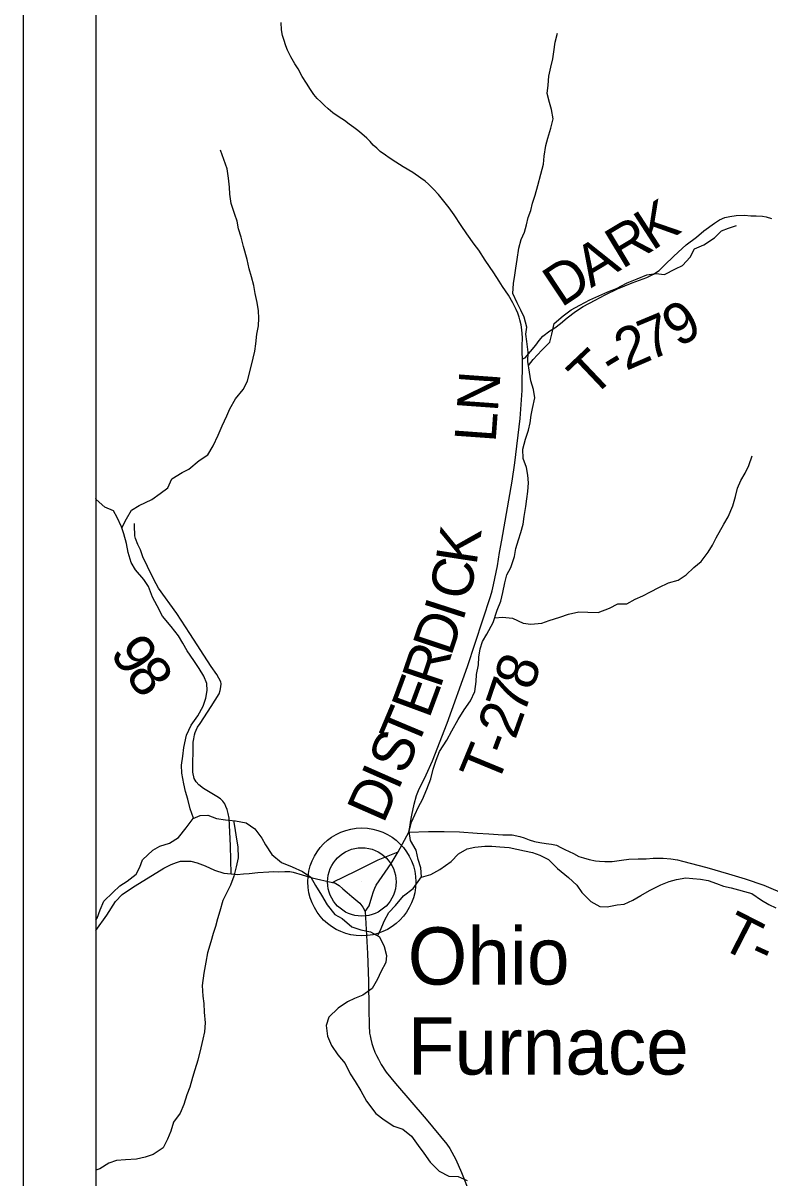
# Model space of a CAD drawing. Extents: x 0 to 44, y -23.8 to 22.
# Drawn here: x 2 to 3.029, y 14.979 to 16.572 of the extents above; entities that cross this region are included whole.
import ezdxf

# ---------------------------------------------------------------- set-up
doc = ezdxf.new("R2010")
doc.units = 0
for name, color, linetype in [('Default', 7, 'Continuous'), ('GM_X_County_Road', 7, 'Continuous'), ('GM_X_County_Text', 7, 'Continuous'), ('GM_X_Minor_River', 7, 'Continuous'), ('GM_X_Township_Road', 7, 'Continuous'), ('GM_X_Township_Road_Text', 7, 'Continuous'), ('GM_X_Unincorporated', 7, 'Continuous'), ('GM_X_Unincorporated_Location', 7, 'Continuous'), ('GM_X_Unincorporated_Text', 7, 'Continuous'), ('SH_Cut_Line', 7, 'Continuous'), ('SH_Data', 7, 'Continuous')]:
    doc.layers.add(name, color=color, linetype=linetype)

msp = doc.modelspace()

# ---------------------------------------------------------------- linework, layer by layer
at = {"layer": 'Default'}
msp.add_lwpolyline([(2.3497, 20.9), (2.1, 20.9), (2.1, 14.1), (2.838, 14.1), (3.0317, 14.1856), (3.8639, 14.5533), (4.3443, 14.7655), (4.4538, 14.8144), (4.856, 14.9939), (4.5387, 15.7097), (4.3476, 16.1408), (4.1422, 16.6361), (4.026, 16.9163), (3.7907, 17.4383), (3.763, 17.5087), (3.455, 18.29), (3.1789, 18.9421), (3.1321, 19.0527), (3.0496, 19.2474), (3.0092, 19.3427), (2.8013, 19.8369), (2.472, 20.6113)], close=True, dxfattribs=at)
at = {"layer": 'GM_X_County_Road'}
msp.add_lwpolyline([(2.1, 15.3207), (2.1152, 15.3415), (2.1275, 15.3607), (2.1364, 15.37), (2.152, 15.3807), (2.1722, 15.3933), (2.1939, 15.4064), (2.204, 15.4117), (2.2112, 15.4141), (2.2167, 15.4159), (2.224, 15.4163), (2.2312, 15.4161), (2.2399, 15.4137), (2.2511, 15.4096), (2.2636, 15.4038), (2.2765, 15.3997), (2.2866, 15.3987), (2.2951, 15.3979), (2.3038, 15.3985), (2.3117, 15.3993), (2.3236, 15.4004), (2.3386, 15.4014), (2.3453, 15.4018), (2.3519, 15.4016), (2.3606, 15.402), (2.3675, 15.402), (2.3721, 15.4008), (2.3847, 15.3973), (2.3984, 15.3929), (2.4265, 15.3869), (2.4285, 15.3866), (2.4354, 15.3824), (2.4407, 15.3779), (2.4465, 15.3729), (2.4532, 15.3672), (2.4639, 15.3581), (2.4684, 15.3526), (2.4716, 15.3466), (2.4744, 15.2888), (2.4758, 15.2504), (2.4764, 15.2126), (2.4768, 15.1893), (2.4775, 15.179), (2.4783, 15.175), (2.4793, 15.1707), (2.4805, 15.1645), (2.4823, 15.1592), (2.4849, 15.1529), (2.4868, 15.1479), (2.4896, 15.1432), (2.4936, 15.1355), (2.5003, 15.1252), (2.513, 15.1095), (2.5557, 15.0601), (2.5838, 15.0256), (2.5882, 15.0199), (2.5965, 15.0046), (2.6042, 14.9868), (2.6157, 14.9579)], dxfattribs=at)
at = {"layer": 'GM_X_Minor_River'}
for points in [[(2.7301, 16.5227), (2.7313, 16.5322), (2.7332, 16.5455), (2.7367, 16.558)], [(2.4886, 15.313), (2.492, 15.3199), (2.4981, 15.3343), (2.5039, 15.3453), (2.5134, 15.3551), (2.5244, 15.3683), (2.5377, 15.3785), (2.5492, 15.3943), (2.5481, 15.4068), (2.5444, 15.4186), (2.5418, 15.4312), (2.534, 15.4445), (2.5322, 15.457), (2.5353, 15.4699), (2.5399, 15.4801), (2.5449, 15.4911), (2.5502, 15.5013), (2.5564, 15.5153), (2.5621, 15.5297), (2.5652, 15.5429), (2.5691, 15.5554), (2.5737, 15.5675), (2.584, 15.583), (2.5909, 15.5959), (2.5997, 15.6113), (2.6077, 15.625), (2.6165, 15.6374), (2.6226, 15.6499), (2.6242, 15.6639), (2.625, 15.6734), (2.6274, 15.6867), (2.6282, 15.6973), (2.6301, 15.709), (2.6332, 15.7189), (2.639, 15.7291), (2.6478, 15.7453), (2.6535, 15.7624), (2.6582, 15.7745), (2.6613, 15.7866), (2.664, 15.7998), (2.6667, 15.8112), (2.6721, 15.821), (2.6774, 15.8362), (2.679, 15.8475), (2.6825, 15.8593), (2.686, 15.8695), (2.6891, 15.8809), (2.6906, 15.8915), (2.693, 15.9051), (2.6942, 15.9157), (2.6958, 15.926), (2.6966, 15.9377), (2.6955, 15.9483), (2.6937, 15.959), (2.6892, 15.9715), (2.6886, 15.9844), (2.6924, 15.998), (2.6963, 16.0105), (2.699, 16.0208), (2.7002, 16.031), (2.7021, 16.0405), (2.7053, 16.0552), (2.7034, 16.0666), (2.6997, 16.0784), (2.6979, 16.0905), (2.6957, 16.105), (2.6962, 16.1182), (2.694, 16.1327), (2.6929, 16.1429), (2.6941, 16.1524), (2.6904, 16.1664), (2.686, 16.176), (2.6811, 16.1862), (2.6751, 16.1992), (2.676, 16.2128), (2.6779, 16.2242), (2.6791, 16.234), (2.6807, 16.2458), (2.6831, 16.2617), (2.6866, 16.2734), (2.6912, 16.2836), (2.6939, 16.2939), (2.6962, 16.3037), (2.6997, 16.3136), (2.702, 16.3238), (2.7055, 16.3348), (2.7093, 16.348), (2.7136, 16.3635), (2.7171, 16.3775), (2.7183, 16.3885), (2.7206, 16.4029), (2.7233, 16.4132), (2.7272, 16.4272), (2.7303, 16.44), (2.7281, 16.4526), (2.7255, 16.4625), (2.7222, 16.4746), (2.7234, 16.4864), (2.7246, 16.4989), (2.7273, 16.511), (2.7301, 16.5227)], [(2.1359, 15.8757), (2.1427, 15.8883), (2.1496, 15.9004), (2.1598, 15.9068), (2.1773, 15.915), (2.189, 15.9233), (2.1993, 15.9308), (2.205, 15.9433), (2.2191, 15.952), (2.2286, 15.9568), (2.2426, 15.9689), (2.2544, 15.9764), (2.262, 15.9889), (2.2686, 16.0036), (2.2743, 16.0165), (2.2808, 16.0301), (2.285, 16.0399), (2.2927, 16.0535), (2.3034, 16.0668), (2.3091, 16.0781), (2.3172, 16.1099), (2.3192, 16.1194), (2.3208, 16.1296), (2.322, 16.1429), (2.3243, 16.1542), (2.3248, 16.1649), (2.3244, 16.1751), (2.3226, 16.1865), (2.32, 16.199), (2.3178, 16.21), (2.3149, 16.2218), (2.3116, 16.2332), (2.309, 16.2461), (2.3038, 16.264), (2.3005, 16.2765), (2.2968, 16.2883), (2.2949, 16.2986), (2.2916, 16.3081), (2.2868, 16.3233), (2.285, 16.3358), (2.2843, 16.3456), (2.2832, 16.3582), (2.281, 16.3707), (2.2766, 16.384), (2.2721, 16.3965)], [(2.6966, 16.0996), (2.7029, 16.108), (2.7147, 16.1208), (2.7258, 16.1321), (2.7285, 16.1431), (2.732, 16.1575), (2.7445, 16.1684), (2.7552, 16.1763), (2.7673, 16.1831), (2.781, 16.1902), (2.806, 16.2014), (2.8177, 16.2059), (2.8325, 16.2138), (2.8462, 16.2194), (2.8598, 16.2246), (2.8719, 16.2268), (2.884, 16.2252), (2.8992, 16.2331), (2.9087, 16.2376), (2.9194, 16.2493), (2.9255, 16.2606), (2.938, 16.2662), (2.9528, 16.2756), (2.9627, 16.2854), (2.9722, 16.2891), (2.9832, 16.2929)], [(2.65, 15.7518), (2.6607, 15.7528), (2.6743, 15.7512), (2.689, 15.7443), (2.6996, 15.7431), (2.7147, 15.7442), (2.7249, 15.7479), (2.7397, 15.7527), (2.7518, 15.7568), (2.7658, 15.7598), (2.7783, 15.7597), (2.7927, 15.7589), (2.8082, 15.7652), (2.8196, 15.7708), (2.8321, 15.7711), (2.8435, 15.7775), (2.8541, 15.782), (2.8647, 15.7876), (2.8761, 15.7936), (2.8894, 15.8), (2.903, 15.8037), (2.914, 15.8112), (2.9243, 15.821), (2.9345, 15.8293), (2.9441, 15.8421), (2.9502, 15.852), (2.9552, 15.8618), (2.9659, 15.8807), (2.9716, 15.8909), (2.9781, 15.906), (2.982, 15.9189), (2.9847, 15.9303), (2.9893, 15.9412), (2.995, 15.9514), (3, 15.9617), (3.0046, 15.9749)], [(2.235, 15.4754), (2.2302, 15.4884), (2.2269, 15.5017), (2.2236, 15.5123), (2.2214, 15.5226), (2.2188, 15.5374), (2.2181, 15.5484), (2.2201, 15.5609), (2.2213, 15.5727), (2.2252, 15.5897), (2.2317, 15.6037), (2.2408, 15.6165), (2.2481, 15.6298), (2.252, 15.6411), (2.2535, 15.6517), (2.2532, 15.6612), (2.2491, 15.6711), (2.2428, 15.6818), (2.2353, 15.6928), (2.2263, 15.7061), (2.2199, 15.7168), (2.2143, 15.7267), (2.2042, 15.7397), (2.1921, 15.7538), (2.1847, 15.7682), (2.1783, 15.78), (2.1727, 15.7948), (2.1664, 15.8047), (2.1551, 15.8177), (2.1487, 15.828), (2.145, 15.8417), (2.1425, 15.8542), (2.1388, 15.8675), (2.1354, 15.877), (2.1298, 15.8899), (2.1246, 15.8994), (2.1125, 15.9041), (2.1009, 15.9151), (2.1, 15.9164)], [(2.1, 15.335), (2.1019, 15.3375), (2.1061, 15.3492), (2.1111, 15.3609), (2.1236, 15.373), (2.1335, 15.382), (2.1434, 15.3884), (2.1559, 15.3982), (2.1609, 15.408), (2.1647, 15.4179), (2.1788, 15.4314), (2.1883, 15.4367), (2.2019, 15.4408), (2.2141, 15.4487), (2.2248, 15.4619), (2.2343, 15.4751), (2.2438, 15.4792), (2.2544, 15.4795), (2.2664, 15.4749), (2.2789, 15.4729), (2.2929, 15.4717), (2.3076, 15.469), (2.3193, 15.4609), (2.329, 15.448), (2.3339, 15.4385), (2.3429, 15.4255)], [(2.29, 15.472), (2.2917, 15.4615), (2.2935, 15.4493), (2.2961, 15.4357), (2.2964, 15.4209), (2.2936, 15.4084), (2.2902, 15.3955), (2.2859, 15.383), (2.2809, 15.3728), (2.2752, 15.3618), (2.2713, 15.3471), (2.2679, 15.3365), (2.2651, 15.3262), (2.2617, 15.3164), (2.2586, 15.305), (2.254, 15.2899), (2.2516, 15.277), (2.2492, 15.2615), (2.2469, 15.2448), (2.2475, 15.23), (2.249, 15.2198), (2.2493, 15.208), (2.2511, 15.1932), (2.2499, 15.1807), (2.2479, 15.1708), (2.2448, 15.1587), (2.2409, 15.1417), (2.2367, 15.1284), (2.2336, 15.1178), (2.2297, 15.1042), (2.2255, 15.094), (2.2217, 15.0807), (2.2163, 15.0686), (2.2071, 15.0561), (2.2037, 15.0437), (2.1991, 15.0327), (2.1929, 15.0206), (2.1793, 15.0116), (2.1683, 15.0078), (2.1561, 15.0049), (2.141, 15.0042), (2.1285, 15.0035), (2.1183, 14.9994), (2.1058, 14.9919), (2.1, 14.9898)], [(2.5489, 15.3939), (2.5621, 15.3977), (2.5742, 15.4044), (2.5898, 15.4157), (2.6, 15.4263), (2.6122, 15.433), (2.6224, 15.4356), (2.6364, 15.4367), (2.6462, 15.4366), (2.6568, 15.4358), (2.6697, 15.4349), (2.6908, 15.4303), (2.7018, 15.4279), (2.7123, 15.4244), (2.724, 15.4183), (2.7364, 15.4061), (2.7515, 15.3935), (2.7631, 15.3828), (2.7699, 15.3729), (2.7823, 15.3603), (2.7947, 15.3534), (2.8049, 15.353), (2.8186, 15.3559), (2.8284, 15.357), (2.8402, 15.3622), (2.8512, 15.3686), (2.8633, 15.3757), (2.8789, 15.3836), (2.8902, 15.3881), (2.9005, 15.3907), (2.9133, 15.3929), (2.9232, 15.3924), (2.9337, 15.3912), (2.9443, 15.3893), (2.9556, 15.3854), (2.9654, 15.3816), (2.9756, 15.3792), (3.0043, 15.3715), (3.0175, 15.3623), (3.0277, 15.3565), (3.0375, 15.3516)], [(2.3429, 15.4255), (2.3561, 15.4144), (2.3708, 15.4083), (2.3851, 15.4018), (2.3964, 15.3941), (2.4028, 15.3827), (2.4114, 15.3694), (2.4189, 15.3557), (2.4297, 15.3427), (2.4399, 15.337), (2.4531, 15.3255), (2.4655, 15.3212), (2.4788, 15.3185), (2.4912, 15.3116), (2.4975, 15.2983), (2.5009, 15.2861), (2.4997, 15.2763), (2.4932, 15.2634), (2.4886, 15.2536), (2.4809, 15.2407), (2.4684, 15.2313), (2.4566, 15.2269), (2.4472, 15.222), (2.4342, 15.2133), (2.4213, 15.2009), (2.4178, 15.1895), (2.4193, 15.1747), (2.4252, 15.1618), (2.4338, 15.1489), (2.444, 15.137), (2.4507, 15.123), (2.4578, 15.1123), (2.4653, 15.0994), (2.4732, 15.0853), (2.4863, 15.0681), (2.4976, 15.0593), (2.5108, 15.0505), (2.5232, 15.0463), (2.5353, 15.0367), (2.5446, 15.0242), (2.5521, 15.0135), (2.5608, 15.0009), (2.5732, 14.9887), (2.5867, 14.9818), (2.5996, 14.981), (2.612, 14.9756)]]:
    msp.add_lwpolyline(points, dxfattribs=at)
at = {"layer": 'GM_X_Township_Road'}
for points in [[(2.3646, 16.5346), (2.3621, 16.5405), (2.3592, 16.5492), (2.3573, 16.5547), (2.356, 16.5626), (2.3558, 16.5728)], [(2.4716, 15.3466), (2.4768, 15.3543), (2.4805, 15.3668), (2.4827, 15.3743), (2.4847, 15.3791), (2.4866, 15.383), (2.495, 15.3949), (2.5074, 15.4127), (2.5169, 15.4291), (2.5315, 15.4562), (2.5324, 15.4606), (2.5332, 15.4657), (2.5341, 15.4701), (2.5355, 15.4797), (2.5389, 15.4946), (2.5422, 15.5067), (2.546, 15.5159), (2.5502, 15.5245), (2.5556, 15.5352), (2.5644, 15.5544), (2.5843, 15.6064), (2.6124, 15.6845), (2.644, 15.781), (2.6465, 15.7889), (2.6484, 15.7971), (2.6536, 15.8233), (2.6565, 15.8419), (2.6597, 15.8587), (2.6739, 15.9401), (2.6777, 15.9655), (2.6848, 16.0268), (2.6877, 16.0651), (2.6883, 16.1088), (2.6877, 16.1177), (2.6879, 16.1263), (2.6881, 16.1385), (2.6873, 16.1491), (2.6862, 16.1556), (2.6845, 16.1625), (2.6835, 16.1663), (2.6816, 16.172), (2.6795, 16.1767), (2.6748, 16.1859), (2.6689, 16.1967), (2.6609, 16.2087), (2.6561, 16.2162), (2.6487, 16.2274), (2.6367, 16.2451), (2.6279, 16.2586), (2.6216, 16.267), (2.6114, 16.2813), (2.6039, 16.2927), (2.594, 16.3074), (2.5872, 16.3173), (2.5796, 16.3264), (2.5723, 16.3354), (2.5657, 16.343), (2.5588, 16.3497), (2.554, 16.3538), (2.5483, 16.3582), (2.5369, 16.3658), (2.524, 16.3736), (2.5137, 16.3803), (2.5045, 16.3862), (2.4994, 16.3898), (2.4923, 16.3948), (2.4876, 16.3994), (2.4826, 16.4037), (2.4781, 16.4085), (2.4735, 16.4133), (2.467, 16.4192), (2.4613, 16.4237), (2.4558, 16.4279), (2.4493, 16.4327), (2.443, 16.4374), (2.4356, 16.4424), (2.427, 16.4481), (2.4204, 16.4538), (2.4152, 16.4582), (2.4101, 16.4633), (2.4053, 16.4681), (2.4007, 16.4736), (2.396, 16.4805), (2.3905, 16.489), (2.3848, 16.4984), (2.379, 16.5087), (2.3747, 16.5159), (2.3689, 16.5252), (2.3659, 16.5317), (2.3646, 16.5346)], [(2.6883, 16.1088), (2.6921, 16.1103), (2.7068, 16.1277), (2.7114, 16.1344), (2.7164, 16.1403), (2.7259, 16.1476), (2.733, 16.1516), (2.7407, 16.1577), (2.7499, 16.1654), (2.7614, 16.174), (2.7719, 16.1809), (2.7885, 16.1899), (2.8023, 16.197), (2.8192, 16.2056), (2.8395, 16.2138), (2.8594, 16.2209), (2.8686, 16.2255), (2.8764, 16.2307), (2.8844, 16.2383), (2.8963, 16.2498), (2.9026, 16.2561), (2.9139, 16.2663), (2.9281, 16.2768), (2.9382, 16.2852), (2.9528, 16.2961), (2.9599, 16.3005), (2.9673, 16.3036), (2.974, 16.3051), (2.9828, 16.3065), (2.9941, 16.3069), (3.0031, 16.3063), (3.0104, 16.3061), (3.019, 16.3055), (3.0242, 16.3046), (3.0315, 16.3023)], [(2.2866, 15.3987), (2.2858, 15.4371), (2.284, 15.4753), (2.2826, 15.482), (2.2812, 15.4875), (2.2794, 15.4917), (2.2779, 15.4952), (2.2753, 15.4988), (2.2719, 15.502), (2.2668, 15.5055), (2.2484, 15.5162), (2.242, 15.5212), (2.2385, 15.5257), (2.2357, 15.5303), (2.2341, 15.539), (2.2345, 15.5801), (2.2351, 15.5847), (2.2361, 15.5902), (2.2371, 15.5936), (2.2385, 15.5966), (2.2405, 15.6009), (2.2438, 15.6061), (2.259, 15.6293), (2.2701, 15.6468), (2.2715, 15.6516), (2.2725, 15.6567), (2.2731, 15.6605), (2.2725, 15.6635), (2.267, 15.6736), (2.2593, 15.6844), (2.2298, 15.73), (2.212, 15.7575), (2.1866, 15.7927), (2.1803, 15.8044), (2.1716, 15.8224), (2.1651, 15.8358), (2.1617, 15.8455), (2.1583, 15.8527), (2.155, 15.861), (2.1542, 15.8649), (2.154, 15.8685), (2.1534, 15.8752), (2.1536, 15.882)], [(2.5315, 15.4562), (2.5589, 15.4569), (2.5803, 15.4569), (2.6012, 15.4567), (2.6256, 15.4549), (2.6418, 15.4537), (2.661, 15.4525), (2.6739, 15.4523), (2.6844, 15.4503), (2.6907, 15.4483), (2.6972, 15.4456), (2.7049, 15.4432), (2.7123, 15.4418), (2.721, 15.4406), (2.7281, 15.4394), (2.735, 15.4381), (2.7412, 15.4351), (2.7465, 15.4323), (2.7524, 15.4295), (2.7584, 15.4268), (2.7661, 15.4224), (2.7724, 15.4206), (2.7799, 15.4185), (2.7889, 15.4165), (2.7944, 15.4159), (2.8015, 15.4157), (2.8118, 15.4157), (2.8249, 15.4175), (2.8346, 15.4189), (2.8476, 15.4194), (2.8587, 15.4194), (2.8684, 15.4204), (2.8823, 15.4202), (2.8926, 15.4191), (2.9017, 15.4179), (2.9086, 15.4163), (2.9422, 15.4076), (2.9721, 15.3985), (2.9951, 15.3919), (3.0208, 15.3832), (3.0521, 15.3696)], [(2.4265, 15.3869), (2.4304, 15.3892), (2.4393, 15.3933), (2.4627, 15.4048), (2.4894, 15.4179), (2.5169, 15.4291)]]:
    msp.add_lwpolyline(points, dxfattribs=at)
at = {"layer": 'GM_X_Unincorporated'}
for radius in [0.0744, 0.0472]:
    msp.add_circle((2.4668, 15.3875), radius, dxfattribs=at)
at = {"layer": 'GM_X_Unincorporated_Location'}
msp.add_line((2.4668, 15.3875), (2.4668, 15.3875), dxfattribs=at)
at = {"layer": 'SH_Cut_Line'}
msp.add_lwpolyline([(2.1, 20.9), (2.1, 14.1), (2.838, 14.1), (3.0317, 14.1856), (3.8639, 14.5533), (4.3443, 14.7655), (4.4538, 14.8144), (4.856, 14.9939), (4.5387, 15.7097), (4.3476, 16.1408), (4.1422, 16.6361)], dxfattribs=at)
at = {"layer": 'SH_Data'}
for p, q in [((2, 21), (2, 14)), ((2.1, 20.9), (2.1, 14.1))]:
    msp.add_line(p, q, dxfattribs=at)

# ---------------------------------------------------------------- texts
at = {"layer": 'GM_X_County_Text'}
msp.add_text('SCIOTO COUNTY', height=0.189394, rotation=23.8999, dxfattribs=at).set_placement((2.9443, 14.3021))
at = {"layer": 'GM_X_Township_Road_Text'}
for s, height, rotation, p in [('K', 0.0568, 32.8784, (2.867, 16.2572)), ('R', 0.0568, 31.1063, (2.8254, 16.2321)), ('A', 0.0568, 31.2377, (2.7827, 16.2062)), ('D', 0.0568, 33.586, (2.7416, 16.1789)), ('9', 0.0568, 31.1942, (2.9033, 16.1235)), ('7', 0.0568, 22.6755, (2.8628, 16.1058)), ('2', 0.0568, 23.3985, (2.8309, 16.092)), ('T', 0.0568, 43.4604, (2.7845, 16.0535)), ('-', 0.0568, 31.3674, (2.8128, 16.0808)), ('LN', 0.05682, 85.878, (2.6511, 15.9926)), ('K', 0.0568, 81.323, (2.6246, 15.823)), ('C', 0.0568, 78.2795, (2.6146, 15.7741)), ('I', 0.0568, 72.1053, (2.6057, 15.7454)), ('D', 0.0568, 71.5771, (2.5897, 15.6974)), ('9', 0.0568, 303.7689, (2.1186, 15.7034)), ('R', 0.0568, 71.4558, (2.5748, 15.6531)), ('8', 0.0568, 306.5294, (2.1398, 15.6718)), ('8', 0.0568, 71.4122, (2.7015, 15.6497)), ('E', 0.0568, 69.679, (2.5594, 15.6114)), ('7', 0.0568, 71.2011, (2.6901, 15.6164)), ('T', 0.0568, 67.1707, (2.5419, 15.5697)), ('2', 0.0568, 70.3461, (2.6781, 15.5825)), ('S', 0.0568, 66.2519, (2.5261, 15.5337)), ('T', 0.0568, 67.5659, (2.6526, 15.5186)), ('-', 0.0568, 69.4644, (2.6696, 15.5598)), ('I', 0.0568, 66.2428, (2.5167, 15.5123)), ('D', 0.0568, 66.2446, (2.4966, 15.4666)), ('T', 0.0568, 332.8753, (2.9573, 15.2984)), ('-', 0.0568, 335.4889, (2.9976, 15.2777))]:
    msp.add_text(s, height=height, rotation=rotation, dxfattribs=at).set_placement(p)
at = {"layer": 'GM_X_Unincorporated_Text'}
for s, p in [('Ohio', (2.53, 15.2459)), ('Furnace', (2.53, 15.1218))]:
    msp.add_text(s, height=0.07898, rotation=0, dxfattribs=at).set_placement(p)

doc.saveas('drawing.dxf')
